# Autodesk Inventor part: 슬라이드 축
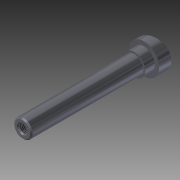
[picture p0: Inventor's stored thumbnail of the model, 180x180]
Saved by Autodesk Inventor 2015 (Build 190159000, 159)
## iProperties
Company: 한국ATC센터
Created: 2014-07
Part Number: 슬라이드 축
Document SubType Name: 모델링
Designer: KYOUNG IL JANG
Mass: 169.348 g
Surface Area: 67.5859 cm^2
Volume: 21.5729 cm^3
Density: 7.85 g/cm^3
Material: Steel, Mild
Appearance: Semi-Polished
Author: KYOUNG IL JANG
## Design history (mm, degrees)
revolve "회전1" stored, may be unused: angle "d4" = 90 deg
sketch "스케치2"
  geometry: L1 (12.5, 0)-(12.5, -17) reference; L2 (-12.5, -17)-(12.5, -17) reference; L3 (-12.5, 0)-(-12.5, -17) reference; L4 (12.5, -5)-(-12.5, -11.699); L5 (-12.5, 0)-(12.5, 0) reference; 1 further point
  constraints: 2 end point, 2 point on line
  dimensions: "d5" = 75 deg angle of L1 L4; "d6" = 5 distance from line of L4.start L5
extrude "돌출1" cut sketch "스케치2" stored distance "d7" = 10; taper "d8" = 0 deg
chamfer "모따기1" distance "d9" = 1; stored, may be unused: second distance "d10" = 2, angle "d11" = 45 deg
fillet "모깎기1" dims "d12" = 0.5
hole "구멍1" diameter "d15" = 6.647; stored, may be unused: countersink angle "d19" = 90 deg, drill point angle "d21" = 118 deg; dims "d13" = 10, "d14" = 10, "d16" = 17, "d17" = 4, "d18" = 2, "d20" = 20
chamfer "모따기2" distance "d22" = 1; stored, may be unused: second distance "d23" = 2, angle "d24" = 45 deg
sketch "스케치3"
  geometry: C1 r 9 at (0, 0); 1 further point
  constraints: 1 centre point, 1 coincident
  dimensions: "d25" = 18 diameter of C1
extrude "돌출2" join sketch "스케치3" distance "d26" = 8; taper "d27" = 0 deg
node "솔리드1"
node "솔리드 본체"
node "곡면 본체"
sketch "스케치1"
  geometry: L1 (0, 100)-(7.5, 100); L2 (7.5, 100)-(7.5, 0); L3 (7.5, 0)-(12.5, 0); L4 (12.5, 0)-(12.5, -17); L5 (12.5, -17)-(0, -17); L6 (0, -17)-(0, 100); 1 further point
  constraints: 12 end point, 2 parallel, 2 point on line, 1 perpendicular, 1 vertical
  dimensions: "d0" = 100 distance from line of L1 point (0, 0); "d1" = 15 diameter of L2 L6; "d2" = 25 diameter of L4 L6; "d3" = 17 distance of L3.end L4.end
node "솔리드2"
